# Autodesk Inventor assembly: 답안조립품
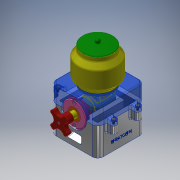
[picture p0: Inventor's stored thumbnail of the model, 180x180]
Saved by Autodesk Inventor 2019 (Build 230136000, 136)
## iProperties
Created: 2022-03
Part Number: 답안조립품
Material: 일반
Document SubType Name: Assembly
Designer: LINE501-4
Author: LINE501-4
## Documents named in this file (11)
- C:\Users\LINE501-4\Desktop\720306V1006\답안조립품.iam
- C:\Users\LINE501-4\Desktop\720306V1006\본체.ipt
- C:\Users\LINE501-4\Desktop\720306V1006\핸들축.ipt
- C:\Users\LINE501-4\Desktop\720306V1006\베어링 부시.ipt
- C:\Users\LINE501-4\Desktop\720306V1006\핸들.ipt
- C:\Users\LINE501-4\Desktop\720306V1006\볼트 M3x12.ipt
- C:\Users\LINE501-4\Desktop\720306V1006\앞커버.ipt
- C:\Users\LINE501-4\Desktop\720306V1006\본체커버.ipt
- C:\Users\LINE501-4\Desktop\720306V1006\볼트 M4x12.ipt
- C:\Users\LINE501-4\Desktop\720306V1006\용기.ipt
- C:\Users\LINE501-4\Desktop\720306V1006\용기캡.ipt
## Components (2 placed, 2 different names)
1. 핸들축:1 — 각도:2, 각도:6
2. 핸들:1 — 각도:2
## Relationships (2: Angle 2)
- 각도:2 [Angle]: 핸들축:1 ↔ 핸들:1
- 각도:6 [Angle]: 핸들축:1
